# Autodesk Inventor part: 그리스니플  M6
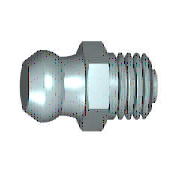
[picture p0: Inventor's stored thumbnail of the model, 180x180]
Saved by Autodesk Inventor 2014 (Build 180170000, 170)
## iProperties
IsCustomPart: 1
Created: 2012-02
Part Number: 그리스니플  M6
Material: 강철, 연강
Description: 그리스 니플에 대한 사양. 제I부: 버튼 머리 그리스 니플 유형 A
Document SubType Name: Modeling
Standard: IS 4009
Designer: mduedu
Standards Organization: IS
Language: ko-KR
Size Designation: M6 원추 짧은
Categories: <MemberInstance><Categories><Category DisplayName="기타 부품" InternalName="5aa15e00-363f-49f2-933f-16f664388e3f" Mnemonic="OTHER"><Category DisplayName="그리스 부속품" I
Density: 1 g/cm^3
Appearance: Steel
Author: mduedu
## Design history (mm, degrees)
sketch "스케치1"
  geometry: L1 (-9.8, 0)-(-9.8, 2.25); L2 (-9.8, 2.25)-(-8.055, 3.194); L3 (-9.8, 0)-(6.2, 0); L4 (6.2, 0)-(6.2, 1.5); L5 (6.2, 1.5)-(5.5, 1.5); L6 (5.5, 1.5)-(5.5, 3); L7 (5.5, 3)-(0, 3); L8 (-13, 0)-(9.4, 0) reference; L9 (0, -1.725)-(0, 10.35) reference; L10 (-3, 3.5)-(0, 3.5); L11 (0, 3.5)-(0, 3); A1 r 3.25 centre (-7.455, 0) between (-5.573, 2.65) and (-8.055, 3.194); A2 r 6 centre (-6.12, 8.625) between (-5.573, 2.65) and (-3, 3.5)
  constraints: 18 end point, 5 perpendicular, 4 point on circle, 2 centre point, 2 parallel, 2 point on line, 1 collinear, 1 vertical
  dimensions: "d0" = 16 distance between parallel lines of L1 L4 (= GL); "d1" = 5.3 diameter of A1.start L3 (= KGB2); "d2" = 0.7 distance between parallel lines of L4 L6 (= PHH); "d3" = 3 diameter of L5 L3 (= 0.5 x NND); "d4" = 6 diameter of L7 L3 (= NND); "d5" = 6.5 dimension on A1 L3 (= KR); "d6" = 4.5 diameter of L1.end L3 (= KGB1); "d7" = 6 radius of A2 (= RBN); "d11" = 7 diameter of L10.start L3 (= SW); "d14" = 3 distance of L10.start L10.end (= KOH); "d15" = 5.5 distance between parallel lines of L6 L11 (= NLG); "d61" = 8.05479 distance from line of L9 L2.end (computed from KGB1, KR, PHH, GL, NLG, VERS); "d62" = 7.45479 distance from line of L9 A1.centre (computed from NLG, GL, PHH, KR, KGB1)
revolve "본체" sketch "스케치1" stored, may be unused: angle "d25" = 90 deg
sketch "스케치2"
  geometry: L1 (2.021, 3.5)-(4.041, 0); L2 (4.041, 0)-(2.021, -3.5); L3 (2.021, -3.5)-(-2.021, -3.5); L4 (-2.021, -3.5)-(-4.041, 0); L5 (-4.041, 0)-(-2.021, 3.5); L6 (-2.021, 3.5)-(2.021, 3.5); C1 r 3.5 at (0, 0) reference; 1 further point
  constraints: 12 end point, 1 coincident, 1 horizontal, 1 tangent, 11 other
extrude "머리" join sketch "스케치2" distance "d17" = 3 (= KOH); taper "d18" = 0 deg
sketch "스케치3"
  geometry: L1 (2.687, 4.041)-(3, 4.041); L2 (3, 4.041)-(3, 3.5); L3 (3, 3.5)-(2.687, 4.041); L4 (0.313, 4.041)-(0, 4.041); L5 (0, 4.041)-(0, 3.5); L6 (0, 3.5)-(0.313, 4.041); L7 (3.6, 0)-(-0.6, 0) reference; L8 (0, 4.041)-(0, 2.021) reference; L9 (0, 4.041)-(3, 4.041) reference; L10 (3, 3.031)-(3, 4.041) reference
  constraints: 12 end point, 4 collinear, 3 perpendicular, 1 horizontal
  dimensions: "d19" = 3.5 distance from line of L5.end L7 (= 0.5 x SW); "d20" = 3.5 distance from line of L2.end L7 (= 0.5 x SW); "d21" = 30 deg angle of L6 L5; "d22" = 30 deg angle of L2 L3
revolve "모따기1" sketch "스케치3" stored, may be unused: angle "d56" = 90 deg
body "Solid1"
fillet "모깎기1" dims "d8" = 0.2 (= RR)
feature "스레드1" dims "d9" = 4.88655 (= NLG - GAL), "d10" = 0
chamfer "모따기2" distance "d23" = 0.61345 (= -0.5 x GD1 + 0.5 x NND); stored, may be unused: angle "d24" = 45 deg, second distance "d59" = 0.61345 (= -0.5 x GD1 + 0.5 x NND)
other parameters: "NLG" = 5.5 [user parameter; used in 4 equation terms], "GL" = 16 [user parameter; used in 3 equation terms], "NND" = 6 [user parameter; used in 4 equation terms], "KGB1" = 4.5 [user parameter; used in 3 equation terms], "KGB2" = 5.3 [user parameter; used in 1 equation term], "VERS" = 0.6 [user parameter; used in 1 equation term], "KR" = 6.5 [user parameter; used in 3 equation terms], "RBN" = 6 [user parameter; used in 1 equation term], "SW" = 7 [user parameter; used in 3 equation terms], "KOH" = 3 [user parameter; used in 2 equation terms], "GAL" = 0.61345 (= 0.61345 x PTC) [user parameter; used in 1 equation term], "FAWI" = 45 deg [user parameter], "PHH" = 0.7 [user parameter; used in 3 equation terms], "GD1" = 4.7731 (= THREADDIA - 1.2269 x PTC) [user parameter; used in 2 equation terms], "RR" = 0.2 [user parameter; used in 1 equation term], "d12" = 0, "d13" = 0, "GUL" = 0.61345 (= 0.61345 x PTC) [user parameter], "DULO" = 1.5 [user parameter], "PTC" = 1 [user parameter; used in 4 equation terms], "GEL" = 5.5 [user parameter], "THREADDIA" = 6 [user parameter; used in 1 equation term], "TOA" = 30 deg [user parameter]
